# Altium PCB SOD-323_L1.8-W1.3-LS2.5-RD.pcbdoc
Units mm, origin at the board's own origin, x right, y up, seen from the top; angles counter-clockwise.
Board outline 16.04 x 14.3 mm, 2 copper layers (Top Layer, Bottom Layer), stack 0 mm thick; 1 components, 0 nets, 2 pads, 0 vias.
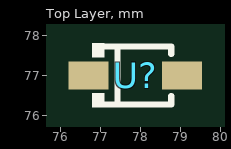
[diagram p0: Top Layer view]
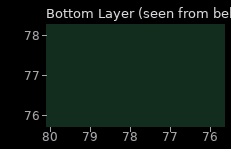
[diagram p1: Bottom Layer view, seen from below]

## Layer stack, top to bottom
Top Layer: signal copper (thickness not stored)
Bottom Layer: signal copper (thickness not stored)

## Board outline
85.895,69.85 69.85,69.85 69.85,84.155 85.895,84.155

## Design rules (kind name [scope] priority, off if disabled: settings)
PasteMaskExpansion "Paste Mask Expansion" [All] p1: expansion=0
SolderMaskExpansion "Solder Mask Expansion" [IsVia] p1: expansion=-25.4 istentingtop=TRUE
SolderMaskExpansion "Solder Mask Expansion" [All] p2: expansion=0.051 istentingtop=FALSE

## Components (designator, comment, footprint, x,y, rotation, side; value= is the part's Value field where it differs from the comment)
U? "" SOD-323_L1.8-W1.3-LS2.5-RD 77.872,77.003 r0 top

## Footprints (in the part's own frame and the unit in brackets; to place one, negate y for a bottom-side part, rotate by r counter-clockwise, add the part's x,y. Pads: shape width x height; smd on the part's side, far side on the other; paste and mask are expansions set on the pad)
SOD-323_L1.8-W1.3-LS2.5-RD [mm]
  rect 1x0.7 smd: 1(-1.172,0) 2(1.172,0)
  silkscreen extent -1.08,-0.8 0.9,0.8

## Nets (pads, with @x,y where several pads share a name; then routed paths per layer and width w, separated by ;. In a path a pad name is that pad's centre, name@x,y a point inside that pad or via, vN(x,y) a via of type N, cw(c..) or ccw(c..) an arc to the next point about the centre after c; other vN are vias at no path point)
pads on no net: U?.1 U?.2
